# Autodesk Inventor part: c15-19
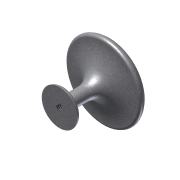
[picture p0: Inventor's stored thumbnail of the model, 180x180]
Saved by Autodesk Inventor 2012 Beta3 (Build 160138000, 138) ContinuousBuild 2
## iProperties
Created: 2011-02
Part Number: c15-19
Material: Default
Document SubType Name: Modeling
Designer: Beta-8540w
Density: 1 g/cm^3
Author: Beta-8540w
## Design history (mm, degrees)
sketch "Sketch1"
  geometry: L1 (0, 0)-(0, 30.48); L2 (4.449, 27.618)-(5.75, 24.764); L3 (5.75, 24.764)-(10.318, 24.764); L4 (11.097, 26.108)-(14.669, 26.108); L5 (0, 0)-(8.89, 0); L6 (6.711, 2.179)-(3.175, 2.179); L7 (3.175, 2.179)-(3.175, 11.402); L8 (10.318, 24.764)-(11.097, 26.108); A1 r 4.889 centre (0, 25.591) between (4.449, 27.618) and (0, 30.48); A2 r 4.384 centre (14.669, 21.724) between (19.05, 21.555) and (14.669, 26.108); A3 r 8.594 centre (11.769, 11.402) between (7.526, 18.876) and (3.175, 11.402); A4 r 20.827 centre (17.809, 0.764) between (19.05, 21.555) and (7.526, 18.876); A5 r 2.179 centre (6.711, 0) between (8.89, 0) and (6.711, 2.179)
  constraints: 16 end point, 10 point on circle, 5 centre point, 5 tangent, 3 parallel, 2 perpendicular, 2 point on line, 1 vertical
  dimensions: "d0" = 17.78 diameter of L5.end L1; "d1" = 6.35 diameter of L7 L1; "d2" = 30.48 distance of L1.start L1.end; "d3" = 38.1 diameter of A2.start L1
revolve "Revolution1" sketch "Sketch1" stored, may be unused: angle "d4" = 90 deg
fillet "Fillet1" dims "d5" = 1.27
hole "Hole1" diameter "d8" = 3.302; stored, may be unused: countersink angle "d12" = 82 deg, drill point angle "d14" = 118 deg; dims "d6" = 25.4, "d7" = 25.4, "d9" = 9.652, "d10" = 9.525, "d11" = 6.35, "d13" = 12.7
body "Solid1"
